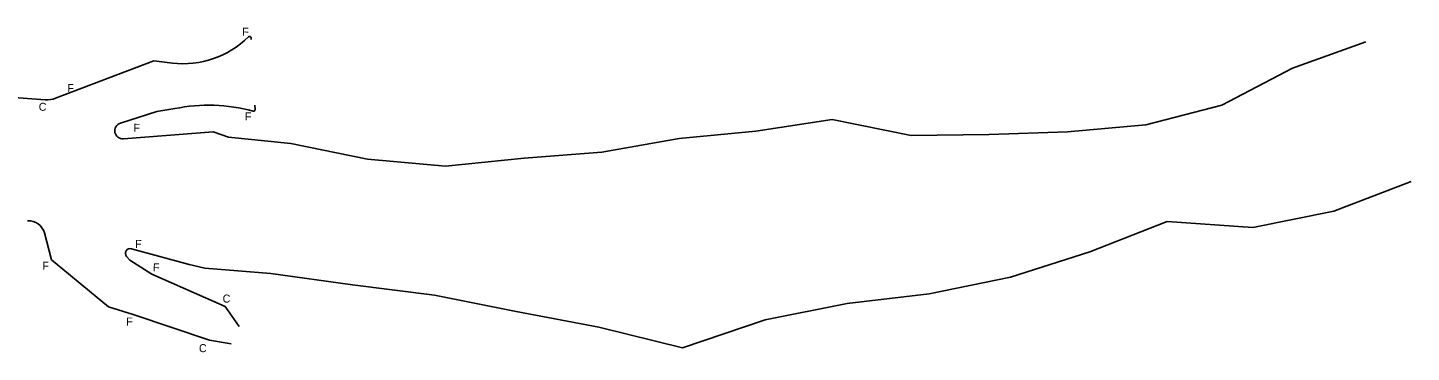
# Model space of a CAD drawing. Extents: x 2166958 to 2178986, y 64620 to 71122.
# Drawn here: x 2174258 to 2175122, y 65828 to 66031 of the extents above; entities that cross this region are included whole.
import ezdxf

# ---------------------------------------------------------------- set-up
doc = ezdxf.new("R2010")
doc.units = 0
doc.layers.add('Default', color=7, linetype='Continuous')

msp = doc.modelspace()

# ---------------------------------------------------------------- linework, layer by layer
at = {"layer": 'Default'}
for p, q in [((2174397.73, 66023.67), (2174397.63, 66024.55)), ((2175048.27, 66005.65), (2175093.98, 66022.08)), ((2174336.93, 66010.25), (2174275.48, 65986.91)), ((2174348.46, 66008.88), (2174336.93, 66010.25)), ((2175004.01, 65982.7), (2175048.27, 66005.65)), ((2174225.66, 65989.18), (2174269.05, 65985.98)), ((2174338.65, 65978.6), (2174315.94, 65971.35)), ((2174350.01, 65980.43), (2174338.65, 65978.6)), ((2174399.97, 65982.58), (2174400.12, 65979.94)), ((2174956.65, 65970.42), (2175004.01, 65982.7)), ((2174712.98, 65966.45), (2174760.53, 65973.74)), ((2174760.53, 65973.74), (2174809.86, 65963.78)), ((2174907.71, 65966.01), (2174956.65, 65970.42)), ((2174317.85, 65961.6), (2174373.9, 65965.97)), ((2174373.9, 65965.97), (2174383.5, 65962.71)), ((2174383.5, 65962.71), (2174422.39, 65958.79)), ((2174616.79, 65953.18), (2174665.05, 65961.73)), ((2174665.05, 65961.73), (2174712.98, 65966.45)), ((2174809.86, 65963.78), (2174858.65, 65964.39)), ((2174858.65, 65964.39), (2174907.71, 65966.01)), ((2174422.39, 65958.79), (2174470.33, 65949.01)), ((2174568.15, 65949.59), (2174616.79, 65953.18)), ((2174470.33, 65949.01), (2174518.98, 65944.49)), ((2174518.98, 65944.49), (2174568.15, 65949.59)), ((2175074.1, 65916.46), (2175122.41, 65934.87)), ((2174921.47, 65891.16), (2174969.86, 65909.93)), ((2174969.86, 65909.93), (2175023.39, 65906.33)), ((2175023.39, 65906.33), (2175074.1, 65916.46)), ((2174268.46, 65902.94), (2174272.92, 65886.08)), ((2174322.87, 65893.04), (2174358.98, 65883.17)), ((2174871.99, 65875.23), (2174921.47, 65891.16)), ((2174272.92, 65886.08), (2174308.43, 65856.73)), ((2174319.78, 65888.22), (2174321.81, 65885.8)), ((2174321.81, 65885.79), (2174335.59, 65877.18)), ((2174358.98, 65883.17), (2174368.77, 65880.96)), ((2174335.59, 65877.18), (2174381.31, 65856.94)), ((2174368.77, 65880.96), (2174409.99, 65877.56)), ((2174409.99, 65877.56), (2174460.99, 65870.43)), ((2174821.3, 65864.82), (2174871.99, 65875.23)), ((2174460.99, 65870.43), (2174512.14, 65864.14)), ((2174308.43, 65856.73), (2174323.98, 65851.98)), ((2174381.31, 65856.93), (2174390.25, 65844.51)), ((2174512.14, 65864.14), (2174563.21, 65853.85)), ((2174718.69, 65848.73), (2174769.96, 65858.8)), ((2174769.96, 65858.8), (2174821.3, 65864.82)), ((2174323.98, 65851.98), (2174371.63, 65835.91)), ((2174563.21, 65853.85), (2174614.8, 65844.06)), ((2174667.02, 65831.23), (2174718.69, 65848.73)), ((2174614.8, 65844.06), (2174667.02, 65831.23)), ((2174371.63, 65835.91), (2174385.23, 65833.61))]:
    msp.add_line(p, q, dxfattribs=at)
for centre, radius, start, end in [((2174355.18, 66066.65), 58.16, 263.36234, 314.47881), ((2174396.63, 66024.44), 1, 6.53767, 134.47881), ((2174270.15, 66000.94), 15, 265.7742, 290.79282), ((2174371.23, 65876.13), 106.44, 74.95445, 101.5004), ((2174399.12, 65979.89), 1, 254.95445, 3.33832), ((2174317.46, 65966.58), 5, 107.70964, 274.45629), ((2174258.79, 65900.38), 10, 14.80973, 94.35725), ((2174322.08, 65890.15), 3, 74.7137, 220.03592)]:
    msp.add_arc(centre, radius, start, end, dxfattribs=at)

# ---------------------------------------------------------------- texts
for s, rotation, p in [('F', 359.37434, (2174392.04, 66025.96)), ('F', 359.37434, (2174282.78, 65990.77)), ('C', 357.88037, (2174264.85, 65979.2)), ('F', 359.37434, (2174393.69, 65973.11)), ('F', 359.37434, (2174324.03, 65965.98)), ('F', 359.37434, (2174325.12, 65893.53)), ('F', 359.37434, (2174267.17, 65879.88)), ('F', 359.37434, (2174336.26, 65878.89)), ('C', 357.88037, (2174379.73, 65859.5)), ('F', 359.37434, (2174319.58, 65845.1)), ('C', 357.88037, (2174364.94, 65828.58))]:
    msp.add_text(s, height=5, rotation=rotation, dxfattribs=at).set_placement(p)

doc.saveas('drawing.dxf')
